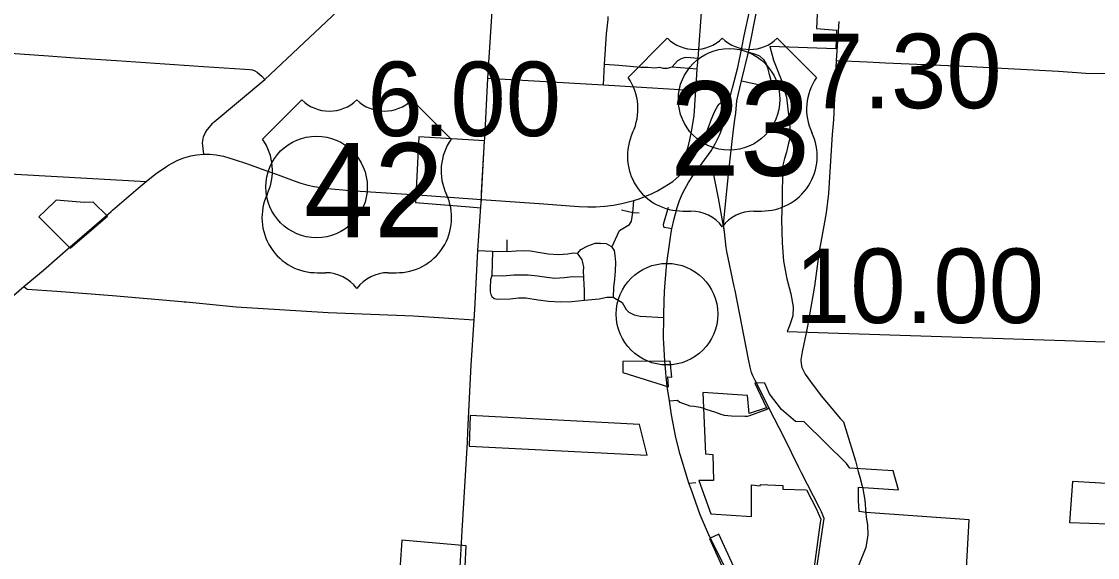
# Model space of a CAD drawing. Extents: x 1729596 to 1934326, y 644115 to 911751.
# Drawn here: x 1799698 to 1815592, y 824548 to 832461 of the extents above; entities that cross this region are included whole.
import ezdxf

# ---------------------------------------------------------------- set-up
doc = ezdxf.new("R2010")
doc.units = 0
for name, color, linetype in [('Default', 7, 'Continuous'), ('GM_X_City_Street', 7, 'Continuous'), ('GM_X_Corporation', 7, 'Continuous'), ('GM_X_County_Road', 7, 'Continuous'), ('GM_X_Township_Road', 7, 'Continuous'), ('GM_X_US_Route', 7, 'Continuous'), ('GM_X_US_Shield', 7, 'Continuous')]:
    doc.layers.add(name, color=color, linetype=linetype)

msp = doc.modelspace()

# ---------------------------------------------------------------- linework, layer by layer
at = {"layer": 'Default'}
for centre in [(1810151, 831311), (1804056, 830019), (1809233, 828140)]:
    msp.add_circle(centre, 750, dxfattribs=at)
at = {"layer": 'GM_X_City_Street'}
for points in [[(1806587, 831627), (1806800, 834898)], [(1809670, 831595), (1809681, 831762), (1809691, 831914), (1809749, 832662), (1809755, 832796), (1809793, 833217), (1809794, 833230), (1809804, 833457), (1809820, 833706)], [(1802546, 830982), (1802546, 830982), (1803292, 831607), (1804693, 832927), (1804742, 832975), (1804765, 832997)], [(1810283, 831379), (1810333, 831585), (1810436, 832008), (1810558, 832630)], [(1808294, 831524), (1808309, 831829), (1808309, 831832), (1808337, 832279), (1808362, 832489), (1808362, 832511), (1808363, 832521), (1808363, 832536)], [(1799244, 832014), (1800095, 831955), (1800485, 831925), (1801101, 831884), (1802386, 831797), (1802997, 831758), (1803072, 831753), (1803111, 831746), (1803145, 831733), (1803179, 831713), (1803219, 831680), (1803250, 831653), (1803292, 831607)], [(1809691, 831914), (1809580, 831927), (1809506, 831928), (1809450, 831914), (1809387, 831881), (1809310, 831790)], [(1810436, 832008), (1810527, 831985), (1810597, 831954), (1810654, 831904), (1810699, 831836), (1810716, 831775), (1810743, 831678), (1810763, 831614), (1810769, 831491)], [(1808309, 831832), (1808519, 831816), (1808689, 831802), (1808840, 831787), (1808952, 831788), (1809052, 831778), (1809122, 831786), (1809178, 831773), (1809238, 831774), (1809310, 831790)], [(1809310, 831790), (1809681, 831762), (1809686, 831761)], [(1806541, 830731), (1806587, 831627)], [(1806587, 831627), (1808294, 831524), (1809660, 831441)], [(1809646, 831231), (1809660, 831441), (1809670, 831595)], [(1810333, 831585), (1810769, 831491)], [(1810506, 827220), (1810502, 827229), (1810482, 827281), (1810461, 827356), (1810438, 827474), (1810238, 828490), (1810225, 828549), (1810117, 829066), (1810105, 829126), (1810080, 829357), (1810068, 829471), (1810135, 830154), (1810144, 830257), (1810215, 830861), (1810235, 831013), (1810251, 831109), (1810267, 831292), (1810283, 831379)], [(1809633, 831074), (1809644, 831214), (1809646, 831231)], [(1802440, 830862), (1802445, 830869), (1802525, 830958), (1802546, 830982)], [(1809570, 830713), (1809577, 830741), (1809602, 830864), (1809633, 831074)], [(1802390, 830503), (1802373, 830668), (1802386, 830760), (1802415, 830824), (1802440, 830862)], [(1809566, 830286), (1809560, 830296), (1809544, 830335), (1809522, 830417), (1809520, 830478), (1809528, 830550), (1809545, 830611), (1809570, 830713)], [(1797010, 830375), (1797016, 830374), (1798754, 830257), (1798814, 830253), (1801541, 830101)], [(1809626, 830197), (1809590, 830248), (1809566, 830286)], [(1810080, 829357), (1809995, 829854)], [(1806208, 824940), (1806284, 826252), (1806292, 826406), (1806341, 827386), (1806384, 828059), (1806393, 828209), (1806439, 829079), (1806485, 829730)], [(1808416, 829127), (1808530, 829374), (1808678, 829466), (1808707, 829512), (1808728, 829643), (1808732, 829692)], [(1808732, 829692), (1808741, 829816)], [(1809198, 829421), (1809185, 829423), (1809182, 829467), (1809256, 829722)], [(1808562, 829683), (1808728, 829643), (1808822, 829637)], [(1809303, 829401), (1809198, 829421)], [(1806872, 829066), (1806871, 829237)], [(1806439, 829079), (1806654, 829072), (1806872, 829066), (1807005, 829076), (1807115, 829079), (1807217, 829073), (1807330, 829057), (1807476, 829033), (1807629, 829022), (1807768, 829031), (1807845, 829047), (1807913, 829041), (1807918, 829041), (1807962, 829095), (1808063, 829150), (1808173, 829189), (1808253, 829190), (1808335, 829183), (1808405, 829142), (1808416, 829127), (1808452, 829081), (1808463, 829005), (1808470, 828909), (1808465, 828773), (1808456, 828658), (1808445, 828536), (1808437, 828393)], [(1806654, 829072), (1806648, 828890), (1806647, 828710), (1806624, 828648), (1806622, 828528), (1806623, 828472), (1806630, 828431), (1806646, 828399), (1806678, 828373), (1806729, 828362), (1806918, 828367), (1807039, 828381), (1807150, 828379), (1807331, 828350), (1807483, 828332), (1807666, 828321), (1807825, 828325), (1808016, 828346), (1808231, 828367), (1808345, 828393), (1808437, 828393), (1808573, 828313), (1808630, 828211), (1808668, 828169), (1808748, 828131), (1808837, 828112), (1809185, 828089)], [(1808016, 828346), (1808014, 828493), (1808007, 828577), (1808002, 828679), (1808002, 828689), (1807999, 828770), (1808006, 828834), (1807990, 828904), (1807981, 828942), (1807913, 829041)], [(1806647, 828710), (1806807, 828708), (1806968, 828719), (1807059, 828719), (1807184, 828720), (1807318, 828708), (1807459, 828688), (1807578, 828673), (1807715, 828680), (1807842, 828698), (1808002, 828689)], [(1799732, 828551), (1799782, 828511), (1800219, 828478), (1801044, 828418), (1802068, 828327), (1802099, 828324), (1802131, 828321)], [(1802131, 828321), (1802871, 828248), (1804230, 828165), (1805488, 828115), (1806384, 828059)], [(1811339, 828131), (1811336, 828114), (1811291, 827864), (1811232, 827586), (1811211, 827467), (1811213, 827409), (1811226, 827353), (1811276, 827254), (1811353, 827144), (1811508, 826935), (1811666, 826747), (1811796, 826596), (1811839, 826549), (1811877, 826439), (1812017, 825974), (1812059, 825816)], [(1809272, 826861), (1809388, 826870), (1809425, 826840), (1809572, 826785), (1809634, 826782), (1809723, 826766), (1809774, 826750)], [(1809554, 825645), (1809661, 825653)], [(1812124, 825562), (1812156, 825394), (1812169, 825198)]]:
    msp.add_lwpolyline(points, dxfattribs=at)
at = {"layer": 'GM_X_Corporation'}
for points in [[(1811450, 832568), (1811442, 832360), (1811738, 832332), (1811727, 832058), (1810753, 832094), (1810804, 831891), (1810920, 831606), (1810996, 831345), (1811047, 830907), (1811046, 830734), (1811021, 830645), (1811000, 830534), (1810970, 830437), (1810937, 830321), (1810936, 829787), (1810922, 829539), (1810934, 829192), (1810954, 828923), (1811004, 828664), (1811064, 828438), (1811096, 828247), (1811090, 828117), (1811049, 827984), (1811009, 827882), (1815869, 827729)], [(1813652, 824301), (1813695, 825106), (1812168, 825213), (1812072, 825227), (1812064, 825391), (1812060, 825586), (1812655, 825545), (1812574, 825827), (1811933, 825865), (1811884, 825933), (1811257, 826553), (1811133, 826557), (1810925, 826731), (1810749, 826965), (1810680, 827120), (1810555, 827125), (1810531, 827123), (1810705, 826759), (1810448, 826674), (1810424, 826940), (1809760, 826986), (1809802, 826080), (1809910, 826070), (1809921, 825683), (1809702, 825683), (1809880, 825193), (1810482, 825151), (1810482, 825622), (1810610, 825608), (1810614, 825626), (1810943, 825609), (1810942, 825555), (1811292, 825549), (1811441, 825259), (1811467, 825200), (1811504, 825116), (1811497, 825064), (1811212, 822957)], [(1815726, 825640), (1815222, 825670), (1815180, 825063), (1815759, 825045)], [(1806224, 823803), (1806265, 824722), (1805316, 824805), (1805265, 824074)], [(1810518, 823765), (1809997, 824891), (1809861, 824827), (1810131, 824227)]]:
    msp.add_lwpolyline(points, dxfattribs=at)
for points in [[(1805516, 829788), (1806315, 829723), (1806482, 829710), (1806539, 830701), (1805565, 830760)], [(1800052, 829671), (1799954, 829576), (1800416, 829114), (1800968, 829587), (1800758, 829796), (1800625, 829787), (1800210, 829823)], [(1808579, 827440), (1808580, 827277), (1809256, 827069), (1809243, 827216), (1809303, 827211), (1809278, 827445)], [(1806310, 826192), (1808940, 826058), (1808827, 826510), (1806327, 826644)]]:
    msp.add_lwpolyline(points, close=True, dxfattribs=at)
at = {"layer": 'GM_X_County_Road'}
for points in [[(1806485, 829730), (1806492, 829835), (1806493, 829933), (1806539, 830701), (1806541, 830731)], [(1809930, 830171), (1809919, 830224)], [(1809995, 829854), (1809930, 830171), (1809930, 830171)], [(1810530, 827173), (1810506, 827220)], [(1811229, 822907), (1811238, 822991), (1811547, 825057), (1811556, 825124), (1811513, 825220), (1811486, 825280), (1811221, 825797), (1811181, 825876), (1810967, 826310), (1810735, 826755), (1810555, 827125), (1810530, 827173)], [(1806145, 823736), (1806150, 823836), (1806167, 824235), (1806208, 824940)]]:
    msp.add_lwpolyline(points, dxfattribs=at)
at = {"layer": 'GM_X_Township_Road'}
for points in [[(1811772, 832461), (1811732, 831884), (1811714, 831436), (1811691, 831009), (1811673, 830792), (1811638, 830245), (1811618, 829920), (1811585, 829634), (1811531, 829335), (1811480, 829070), (1811410, 828555), (1811339, 828131)], [(1811732, 831884), (1812190, 831865), (1812461, 831851), (1813734, 831797), (1813810, 831792), (1815017, 831728), (1815419, 831700), (1815762, 831691), (1815839, 831685)], [(1809774, 826750), (1809808, 826739), (1809950, 826691), (1810029, 826662), (1810079, 826649), (1810185, 826637), (1810382, 826632), (1810424, 826636), (1810455, 826644), (1810697, 826732), (1810735, 826755)], [(1812059, 825816), (1812082, 825733), (1812117, 825600), (1812124, 825562)], [(1812169, 825198), (1812173, 825150), (1812194, 825026), (1812201, 824882), (1812171, 824694), (1812069, 824441), (1812067, 824435)]]:
    msp.add_lwpolyline(points, dxfattribs=at)
at = {"layer": 'GM_X_US_Route'}
for points in [[(1810375, 832252), (1810458, 832634), (1810519, 832855), (1810590, 833042), (1810642, 833161), (1810931, 833769), (1811145, 834201), (1811545, 835017), (1811721, 835387), (1811810, 835583), (1811858, 835709), (1811904, 835901), (1811923, 836046), (1811940, 836302), (1811943, 836419), (1811905, 836674), (1811861, 836825), (1811798, 837006), (1811769, 837090), (1811671, 837289), (1811535, 837559), (1811464, 837713)], [(1810200, 831481), (1810278, 831782), (1810336, 832074), (1810375, 832252)], [(1810161, 831327), (1810200, 831481)], [(1809658, 830240), (1809887, 830554), (1809944, 830656), (1810013, 830794), (1810064, 830924), (1810114, 831096), (1810123, 831139), (1810161, 831327)], [(1810018, 831255), (1810029, 831264), (1810062, 831287), (1810099, 831310), (1810129, 831322), (1810161, 831327)], [(1809806, 830793), (1809817, 830824), (1809875, 830980), (1809883, 831007), (1809924, 831101), (1809942, 831139), (1809965, 831182), (1809982, 831214), (1810002, 831240), (1810018, 831255)], [(1809565, 830366), (1809645, 830481), (1809731, 830633), (1809791, 830753), (1809806, 830793)], [(1801840, 830321), (1801868, 830339), (1801922, 830372), (1802008, 830412), (1802096, 830448), (1802197, 830477), (1802286, 830491), (1802390, 830503), (1802479, 830501), (1802573, 830493), (1802598, 830488)], [(1802598, 830488), (1802682, 830472), (1802838, 830425), (1803021, 830363), (1803306, 830259), (1803490, 830195), (1803724, 830107), (1803823, 830072), (1803927, 830046), (1804023, 830024), (1804119, 830008), (1804217, 829996), (1804391, 829979), (1804546, 829967), (1805540, 829901)], [(1809054, 829941), (1809092, 829962), (1809190, 830018), (1809319, 830101), (1809414, 830184), (1809493, 830273), (1809544, 830335), (1809565, 830366)], [(1801541, 830101), (1801693, 830220), (1801792, 830288), (1801840, 830321)], [(1809448, 829889), (1809465, 829932), (1809500, 829994), (1809550, 830083), (1809626, 830197), (1809658, 830240)], [(1801421, 829999), (1801541, 830101)], [(1801022, 829657), (1801044, 829677), (1801421, 829999)], [(1805540, 829901), (1805687, 829891), (1806492, 829835)], [(1806492, 829835), (1807414, 829767), (1807797, 829742), (1807937, 829731), (1808063, 829726), (1808184, 829726), (1808317, 829734), (1808441, 829749), (1808567, 829774), (1808741, 829816), (1808822, 829845), (1808931, 829885), (1809015, 829920), (1809054, 829941)], [(1809341, 829549), (1809360, 829624), (1809385, 829713), (1809419, 829819), (1809448, 829889)], [(1800425, 829142), (1800450, 829164), (1801022, 829657)], [(1809303, 829401), (1809341, 829549)], [(1809295, 829348), (1809303, 829401)], [(1809248, 829033), (1809295, 829348)], [(1797621, 826760), (1797666, 826798), (1798064, 827135), (1798491, 827497), (1799248, 828136), (1799732, 828551), (1800024, 828792), (1800425, 829142)], [(1809185, 828132), (1809189, 828331), (1809196, 828477), (1809207, 828601), (1809226, 828846), (1809244, 829004), (1809248, 829033)], [(1809185, 827707), (1809181, 827785), (1809185, 828089), (1809185, 828132)], [(1809214, 827282), (1809209, 827339), (1809200, 827447), (1809185, 827707)], [(1809236, 827071), (1809235, 827075), (1809220, 827214), (1809214, 827282)], [(1809539, 825695), (1809427, 826070), (1809364, 826320), (1809297, 826652), (1809272, 826861), (1809236, 827071)], [(1809871, 824842), (1809868, 824846), (1809721, 825180), (1809589, 825557), (1809554, 825645), (1809539, 825695)], [(1810349, 823936), (1810231, 824145), (1810052, 824472), (1809871, 824842)]]:
    msp.add_lwpolyline(points, dxfattribs=at)
at = {"layer": 'GM_X_US_Shield'}
for p, q in [((1809237, 832215), (1808657, 831635)), ((1809237, 832215), (1808657, 831635)), ((1811442, 831635), (1810862, 832215)), ((1811442, 831635), (1810862, 832215)), ((1803839, 831304), (1803259, 830724)), ((1803839, 831304), (1803259, 830724)), ((1806043, 830724), (1805463, 831304)), ((1806043, 830724), (1805463, 831304)), ((1809469, 829663), (1809586, 829663)), ((1809469, 829663), (1809586, 829663)), ((1810514, 829663), (1810630, 829663)), ((1810514, 829663), (1810630, 829663)), ((1804071, 828752), (1804187, 828752)), ((1804071, 828752), (1804187, 828752)), ((1805115, 828752), (1805231, 828752)), ((1805115, 828752), (1805231, 828752))]:
    msp.add_line(p, q, dxfattribs=at)
for centre, radius, start, end in [((1809644, 832629), 580, 225.573, 314.427), ((1809644, 832629), 580, 225.573, 314.427), ((1810456, 832629), 580, 225.573, 314.427), ((1810456, 832629), 580, 225.573, 314.427), ((1807992, 831169), 812, 334.5471, 35.0009), ((1807992, 831169), 812, 334.5471, 35.0009), ((1812107, 831169), 812, 144.9991, 205.4529), ((1812107, 831169), 812, 144.9991, 205.4529), ((1804245, 831718), 580, 225.573, 314.427), ((1804245, 831718), 580, 225.573, 314.427), ((1805057, 831718), 580, 225.573, 314.427), ((1805057, 831718), 580, 225.573, 314.427), ((1809460, 830475), 812, 154.8319, 270.6383), ((1809460, 830475), 812, 154.8319, 270.6383), ((1810639, 830475), 812, 269.3617, 25.1681), ((1810639, 830475), 812, 269.3617, 25.1681), ((1802593, 830258), 812, 334.5471, 35.0009), ((1802593, 830258), 812, 334.5471, 35.0009), ((1806708, 830258), 812, 144.9991, 205.4529), ((1806708, 830258), 812, 144.9991, 205.4529), ((1804062, 829564), 812, 154.8319, 270.6383), ((1804062, 829564), 812, 154.8319, 270.6383), ((1805240, 829564), 812, 269.3617, 25.1681), ((1805240, 829564), 812, 269.3617, 25.1681), ((1809586, 829082), 580, 36.8699, 90), ((1809586, 829082), 580, 36.8699, 90), ((1810514, 829082), 580, 90, 143.1301), ((1810514, 829082), 580, 90, 143.1301), ((1804187, 828172), 580, 36.8699, 90), ((1804187, 828172), 580, 36.8699, 90), ((1805115, 828172), 580, 90, 143.1301), ((1805115, 828172), 580, 90, 143.1301)]:
    msp.add_arc(centre, radius, start, end, dxfattribs=at)

# ---------------------------------------------------------------- texts
at = {"layer": 'Default'}
for s, p in [('7.30', (1811315, 831181)), ('6.00', (1804806, 830769)), ('10.00', (1811122, 828009))]:
    msp.add_text(s, height=1100, dxfattribs=at).set_placement(p)
at = {"layer": 'GM_X_US_Shield'}
for s, p in [('23', (1809275, 830185)), ('23', (1809275, 830185)), ('42', (1803867, 829274)), ('42', (1803867, 829274))]:
    msp.add_text(s, height=1392.2, dxfattribs=at).set_placement(p)

doc.saveas('drawing.dxf')
